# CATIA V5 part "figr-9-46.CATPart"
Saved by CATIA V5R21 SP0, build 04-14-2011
Part number: Part1
Bounding box of the stored display mesh (mm): x -159.661 to 182.627, y -78.048 to 78.048, z 0 to 72.429
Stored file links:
  D:\CATIA V5R21 E-RESOURCES\CATIA-V5R21\catia-v5r21-prt\c09-catia-v5r20-prt\c09-catia-v5r21-figr-9-46.CATPart
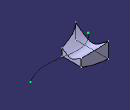
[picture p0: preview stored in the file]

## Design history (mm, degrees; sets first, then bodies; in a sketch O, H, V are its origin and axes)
Body1 (main body)
  Plane1: type Offset, RefPlane yz-plane, Offset 100
  Plane2: type Offset, RefPlane yz-plane, Offset 100, reversed
  Sketch1 on Plane1, origin (100, 0, 0), H (0, 1, 0), V (0, 0, 1)
    point P1 (0, 15.965)
    hyperbola C1
    point P2 (0, 3.0416)
    line L1 (54.8261, 44.8858) -> (54.8261, 0)
    point P5 (54.8261, 0)
    line L2 (-54.8261, 44.8858) -> (-54.8261, 0)
    point P6 (-54.8261, 0)
    line L3 (-54.8261, 0) -> (54.8261, 0)
    coincidence: P1 V, P2 V, P5 H, P6 H
    vertical: L1 V, L2 V
    horizontal: L3 H
  Sketch2 on xy-plane, origin (0, 0, 0), H (1, 0, 0), V (0, 1, 0)
    spline S1 through (-159.6608, -77.1468) (-77.8466, -31.8169) (23.6283, -41.4968) (182.6271, -11.7333)
  Sketch3 on yz-plane, origin (0, 0, 0), H (0, 1, 0), V (0, 0, 1)
    point P1 (0, 18.9787)
    hyperbola C1
    point P2 (0, 2.6681)
    line L1 (48.2237, 37.1764) -> (48.2237, 0)
    point P5 (48.2237, 0)
    line L2 (-43.6563, 34.1546) -> (-43.6563, 0)
    point P6 (-43.6563, 0)
    line L3 (-43.6563, 0) -> (48.2237, 0)
    coincidence: P1 V, P2 V, P5 H, P6 H
    vertical: L1 V, L2 V
    horizontal: L3 H
  Sketch4 on Plane2, origin (-100, 0, 0), H (0, 1, 0), V (0, 0, 1)
    point P1 (0, 140.6052)
    point P2 (0, 41.8972)
    hyperbola C1
    line L1 (78.0478, 72.4293) -> (78.0478, 0)
    point P5 (78.0478, 0)
    line L2 (-78.0478, 72.4293) -> (-78.0478, 0)
    point P6 (-78.0478, 0)
    line L3 (-78.0478, 0) -> (78.0478, 0)
    coincidence: P1 V, P2 V, P5 H, P6 H
    vertical: L1 V, L2 V
    horizontal: L3 H
  Loft1: solid, Sections (Sketch3; Sketch4), Spine Sketch2
  Loft2: solid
